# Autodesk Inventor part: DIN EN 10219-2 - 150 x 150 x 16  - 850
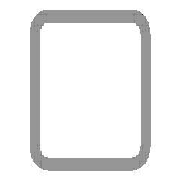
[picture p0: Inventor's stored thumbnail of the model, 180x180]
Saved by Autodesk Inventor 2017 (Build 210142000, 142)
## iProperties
Created: 2017-11
Part Number: DIN EN 10219-2 - 150 x 150 x 16  - 850
Material: Steel, Mild
Description: Cold formed welded structural hollow sections of non-alloy and fine grain structural steel
Document SubType Name: Modeling
Standard: DIN
Designer: iusti
Standard Revision: 2006-07
Standards Organization: DIN
Language: en-US
Size Designation: 150 x 150 x 16
Categories: <MemberInstance><Categories><Category DisplayName="Structural Shapes" InternalName="089c4875-fa83-4c05-b084-43b9cc11f5ed" Mnemonic="GRDR"><CategoryParameter Dis
Stock Number: 150 x 150 x 16
Mass: 49891.9 g
Surface Area: 8094.11 cm^2
Volume: 6355.65 cm^3
Density: 7.85 g/cm^3
Appearance: Semi-Polished
IsCustomPart: 1
G_W: 150.000 mm
G_H: 150.000 mm
G_L: 850.000 mm
+3725B7E9-7AF2-4E59-89A6-3A300E17AA57+CUTDETAIL3: Cut
+D51DAF0C-9B75-4607-A0B5-4213B0D9FE2B+CUTDETAIL4: Cut
_CCFamilyMember: 76
_CCFamilyDisplayName: DIN EN 10219-2 (Square Hollow Section - Cold Formed) - Cold formed welded structural hollow sections of non-alloy and fine grain structural steel
_FrameMemberDoc: Frame Member File
_Version: 15.0.0
_GetPNFromCC: 1
Author: iusti
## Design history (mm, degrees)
node "Start plane"
node "End plane"
sketch "Sketch"
  geometry: L1 (-75, -27)-(-75, 27); L2 (-27, 75)-(27, 75); L3 (75, 27)-(75, -27); L4 (27, -75)-(-27, -75); L5 (-27, 59)-(27, 59); L6 (59, 27)-(59, -27); L7 (27, -59)-(-27, -59); L8 (-59, -27)-(-59, 27); L9 (0, 118.918)-(0, -118.918) reference; L10 (-118.918, 0)-(118.918, 0) reference; A1 r 48 centre (-27, -27) between (-75, -27) and (-27, -75); A2 r 48 centre (-27, 27) between (-27, 75) and (-75, 27); A3 r 48 centre (27, 27) between (75, 27) and (27, 75); A4 r 48 centre (27, -27) between (27, -75) and (75, -27); A5 r 32 centre (-27, 27) between (-27, 59) and (-59, 27); A6 r 32 centre (27, 27) between (59, 27) and (27, 59); A7 r 32 centre (27, -27) between (27, -59) and (59, -27); A8 r 32 centre (-27, -27) between (-59, -27) and (-27, -59)
  constraints: 16 end point, 16 point on circle, 8 centre point, 8 tangent, 4 parallel, 3 equal radius, 2 perpendicular, 7 other
  dimensions: "d7" = 48 radius of A1 (= G_IR); "d10" = 150 distance between parallel lines of L2 L4 (= G_H); "d11" = 150 distance between parallel lines of L1 L3 (= G_W); "d12" = 16 distance between parallel lines of L3 L6 (= G_T); "d15" = 75 distance between parallel lines of L2 L10 (= 0.5 x d10); "d16" = 75 distance between parallel lines of L9 L3 (= 0.5 x d11)
extrude "Body" new body sketch "Sketch" stored distance "d3" = 850 (= G_L); taper "d4" = 0 deg
node "Driven Length"
  sketch "Sketch3"
    geometry: L1 (0, 0)-(10, 0) reference
    constraints: 2 end point, 1 horizontal
  workplane "Work Plane3"
  sketch "Sketch4"
    geometry: L1 (-2, 75)-(12, 75) reference; L2 (-2, 925)-(12, 925) reference
    dimensions: "d18" = 850 distance between parallel lines of L1 L2 (derived)
workplane "Work Plane4"
split "Split1"
workplane "Work Plane5"
split "Split2"
body "Solid1"
other parameters: "G_W" = 150 [user parameter; used in 1 equation term], "G_H" = 150 [user parameter; used in 1 equation term], "G_T" = 16 [user parameter; used in 1 equation term], "G_IR" = 48 [user parameter; used in 1 equation term], "G_L" = 850 (= d18) [user parameter; used in 1 equation term], "G_OFFSET_START" = -75 [user parameter; used in 1 equation term], "G_OFFSET_END" = -110.90437 [user parameter; used in 1 equation term], "d13" = 75 (= -G_OFFSET_START), "d14" = 925 (= G_OFFSET_END + B_L), "B_L" = 1035.90437 [user parameter; used in 1 equation term], "d17" = 90 deg
